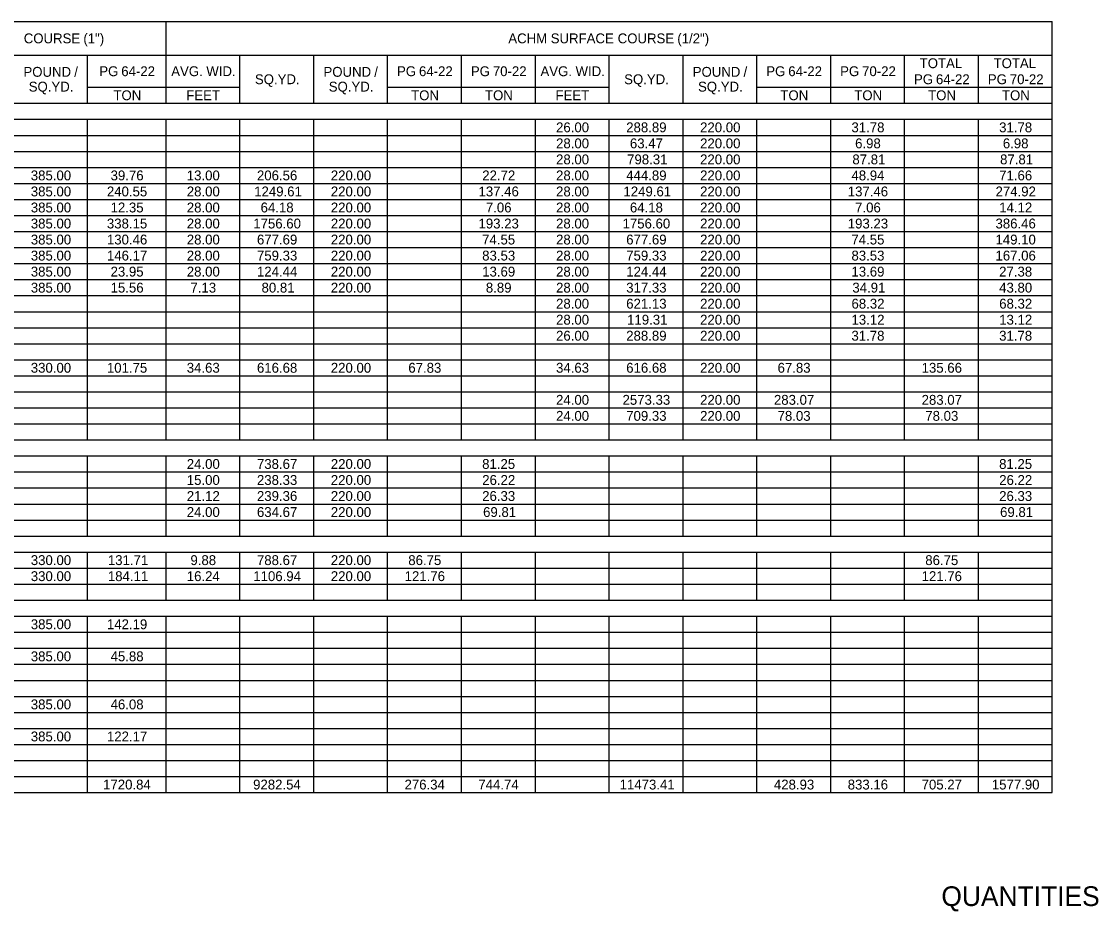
# Model space of a CAD drawing. Extents: x 1197542 to 1207068, y 230488 to 237324.
# Drawn here: x 1202635 to 1203290, y 231726 to 232267 of the extents above; entities that cross this region are included whole.
import ezdxf

# ---------------------------------------------------------------- set-up
doc = ezdxf.new("R2010")
doc.units = 0
doc.layers.add('Default', color=7, linetype='Continuous')
doc.layers.add('R_Annotation', color=7, linetype='Continuous')

msp = doc.modelspace()

# ---------------------------------------------------------------- linework, layer by layer
at = {"layer": 'Default'}
for p, q in [((1201719.44, 232267.45), (1203261.96, 232267.45)), ((1202722.83, 232246.98), (1202722.83, 232267.45)), ((1202722.83, 232217.73), (1202722.83, 232267.45)), ((1203261.96, 231808.23), (1203261.96, 232267.45)), ((1203261.96, 231798.48), (1203261.96, 232267.45)), ((1202088.22, 232246.98), (1203261.96, 232246.98)), ((1202675.09, 232217.73), (1202675.09, 232246.98)), ((1202767.76, 232246.98), (1202812.68, 232246.98)), ((1202767.76, 232217.73), (1202767.76, 232246.98)), ((1202812.68, 232217.73), (1202812.68, 232246.98)), ((1202857.61, 232217.73), (1202857.61, 232246.98)), ((1202902.54, 232217.73), (1202902.54, 232246.98)), ((1202947.47, 232217.73), (1202947.47, 232246.98)), ((1202992.4, 232246.98), (1203037.32, 232246.98)), ((1202992.4, 232217.73), (1202992.4, 232246.98)), ((1203037.32, 232217.73), (1203037.32, 232246.98)), ((1203082.25, 232217.73), (1203082.25, 232246.98)), ((1203127.18, 232217.73), (1203127.18, 232246.98)), ((1203172.11, 232217.73), (1203172.11, 232246.98)), ((1203217.04, 232217.73), (1203217.04, 232246.98)), ((1202675.09, 232227.48), (1202767.76, 232227.48)), ((1202722.83, 232217.73), (1202722.83, 232227.48)), ((1202767.76, 232217.73), (1202767.76, 232227.48)), ((1202857.61, 232227.48), (1202992.4, 232227.48)), ((1202947.47, 232217.73), (1202947.47, 232227.48)), ((1202992.4, 232217.73), (1202992.4, 232227.48)), ((1203082.25, 232227.48), (1203261.96, 232227.48)), ((1201719.44, 232217.73), (1203261.96, 232217.73)), ((1202585.24, 232217.73), (1202767.76, 232217.73)), ((1202767.76, 232217.73), (1202992.4, 232217.73)), ((1202992.4, 232217.73), (1203261.96, 232217.73)), ((1201719.44, 232207.98), (1203261.96, 232207.98)), ((1202675.09, 232012.98), (1202675.09, 232207.98)), ((1202675.09, 232012.98), (1202675.09, 232207.98)), ((1202722.83, 232012.98), (1202722.83, 232207.98)), ((1202722.83, 232012.98), (1202722.83, 232207.98)), ((1202767.76, 232012.98), (1202767.76, 232207.98)), ((1202767.76, 232012.98), (1202767.76, 232207.98)), ((1202812.68, 232012.98), (1202812.68, 232207.98)), ((1202812.68, 232012.98), (1202812.68, 232207.98)), ((1202857.61, 232012.98), (1202857.61, 232207.98)), ((1202857.61, 232012.98), (1202857.61, 232207.98)), ((1202902.54, 232012.98), (1202902.54, 232207.98)), ((1202902.54, 232012.98), (1202902.54, 232207.98)), ((1202947.47, 232012.98), (1202947.47, 232207.98)), ((1202947.47, 232012.98), (1202947.47, 232207.98)), ((1202992.4, 232012.98), (1202992.4, 232207.98)), ((1202992.4, 232012.98), (1202992.4, 232207.98)), ((1203037.32, 232012.98), (1203037.32, 232207.98)), ((1203037.32, 232012.98), (1203037.32, 232207.98)), ((1203082.25, 232012.98), (1203082.25, 232207.98)), ((1203082.25, 232012.98), (1203082.25, 232207.98)), ((1203127.18, 232012.98), (1203127.18, 232207.98)), ((1203127.18, 232012.98), (1203127.18, 232207.98)), ((1203172.11, 232012.98), (1203172.11, 232207.98)), ((1203172.11, 232012.98), (1203172.11, 232207.98)), ((1203217.04, 232012.98), (1203217.04, 232207.98)), ((1203217.04, 232012.98), (1203217.04, 232207.98)), ((1201719.44, 232198.23), (1203261.96, 232198.23)), ((1201719.44, 232188.48), (1203261.96, 232188.48)), ((1201719.44, 232178.73), (1203261.96, 232178.73)), ((1201719.44, 232168.98), (1203261.96, 232168.98)), ((1201719.44, 232159.23), (1203261.96, 232159.23)), ((1201719.44, 232149.48), (1203261.96, 232149.48)), ((1201719.44, 232139.73), (1203261.96, 232139.73)), ((1201719.44, 232129.98), (1203261.96, 232129.98)), ((1201719.44, 232120.23), (1203261.96, 232120.23)), ((1201719.44, 232110.48), (1203261.96, 232110.48)), ((1201719.44, 232100.73), (1203261.96, 232100.73)), ((1201719.44, 232090.98), (1203261.96, 232090.98)), ((1201719.44, 232081.23), (1203261.96, 232081.23)), ((1201719.44, 232071.48), (1203261.96, 232071.48)), ((1201719.44, 232061.73), (1203261.96, 232061.73)), ((1201719.44, 232051.98), (1203261.96, 232051.98)), ((1201719.44, 232042.23), (1203261.96, 232042.23)), ((1201719.44, 232032.48), (1203261.96, 232032.48)), ((1201719.44, 232022.73), (1203261.96, 232022.73)), ((1201719.44, 232012.98), (1202992.4, 232012.98)), ((1201719.44, 232012.98), (1203261.96, 232012.98)), ((1202992.4, 232012.98), (1203037.32, 232012.98)), ((1203037.32, 232012.98), (1203172.11, 232012.98)), ((1203172.11, 232012.98), (1203261.96, 232012.98)), ((1201719.44, 232003.23), (1203261.96, 232003.23)), ((1202675.09, 231954.48), (1202675.09, 232003.23)), ((1202675.09, 231954.48), (1202675.09, 232003.23)), ((1202722.83, 231954.48), (1202722.83, 232003.23)), ((1202722.83, 231954.48), (1202722.83, 232003.23)), ((1202767.76, 231954.48), (1202767.76, 232003.23)), ((1202767.76, 231954.48), (1202767.76, 232003.23)), ((1202812.68, 231954.48), (1202812.68, 232003.23)), ((1202812.68, 231954.48), (1202812.68, 232003.23)), ((1202857.61, 231954.48), (1202857.61, 232003.23)), ((1202857.61, 231954.48), (1202857.61, 232003.23)), ((1202902.54, 231954.48), (1202902.54, 232003.23)), ((1202902.54, 231954.48), (1202902.54, 232003.23)), ((1202947.47, 231954.48), (1202947.47, 232003.23)), ((1202947.47, 231954.48), (1202947.47, 232003.23)), ((1202992.4, 231954.48), (1202992.4, 232003.23)), ((1202992.4, 231954.48), (1202992.4, 232003.23)), ((1203037.32, 231954.48), (1203037.32, 232003.23)), ((1203037.32, 231954.48), (1203037.32, 232003.23)), ((1203082.25, 231954.48), (1203082.25, 232003.23)), ((1203082.25, 231954.48), (1203082.25, 232003.23)), ((1203127.18, 231954.48), (1203127.18, 232003.23)), ((1203127.18, 231954.48), (1203127.18, 232003.23)), ((1203172.11, 231954.48), (1203172.11, 232003.23)), ((1203172.11, 231954.48), (1203172.11, 232003.23)), ((1203217.04, 231954.48), (1203217.04, 232003.23)), ((1203217.04, 231954.48), (1203217.04, 232003.23)), ((1201719.44, 231993.48), (1203261.96, 231993.48)), ((1201719.44, 231983.73), (1203261.96, 231983.73)), ((1201719.44, 231973.98), (1203261.96, 231973.98)), ((1201719.44, 231964.23), (1203261.96, 231964.23)), ((1201719.44, 231954.48), (1203261.96, 231954.48)), ((1201719.44, 231954.48), (1203261.96, 231954.48)), ((1201719.44, 231944.73), (1203261.96, 231944.73)), ((1202675.09, 231915.48), (1202675.09, 231944.73)), ((1202675.09, 231915.48), (1202675.09, 231944.73)), ((1202722.83, 231915.48), (1202722.83, 231944.73)), ((1202722.83, 231915.48), (1202722.83, 231944.73)), ((1202767.76, 231915.48), (1202767.76, 231944.73)), ((1202767.76, 231915.48), (1202767.76, 231944.73)), ((1202812.68, 231915.48), (1202812.68, 231944.73)), ((1202812.68, 231915.48), (1202812.68, 231944.73)), ((1202857.61, 231915.48), (1202857.61, 231944.73)), ((1202857.61, 231915.48), (1202857.61, 231944.73)), ((1202902.54, 231915.48), (1202902.54, 231944.73)), ((1202902.54, 231915.48), (1202902.54, 231944.73)), ((1202947.47, 231915.48), (1202947.47, 231944.73)), ((1202947.47, 231915.48), (1202947.47, 231944.73)), ((1202992.4, 231915.48), (1202992.4, 231944.73)), ((1202992.4, 231915.48), (1202992.4, 231944.73)), ((1203037.32, 231915.48), (1203037.32, 231944.73)), ((1203037.32, 231915.48), (1203037.32, 231944.73)), ((1203082.25, 231915.48), (1203082.25, 231944.73)), ((1203082.25, 231915.48), (1203082.25, 231944.73)), ((1203127.18, 231915.48), (1203127.18, 231944.73)), ((1203127.18, 231915.48), (1203127.18, 231944.73)), ((1203172.11, 231915.48), (1203172.11, 231944.73)), ((1203172.11, 231915.48), (1203172.11, 231944.73)), ((1203217.04, 231915.48), (1203217.04, 231944.73)), ((1203217.04, 231915.48), (1203217.04, 231944.73)), ((1201719.44, 231934.98), (1203261.96, 231934.98)), ((1201719.44, 231925.23), (1203261.96, 231925.23)), ((1201719.44, 231915.48), (1202992.4, 231915.48)), ((1201719.44, 231915.48), (1203261.96, 231915.48)), ((1202992.4, 231915.48), (1203037.32, 231915.48)), ((1203037.32, 231915.48), (1203172.11, 231915.48)), ((1203172.11, 231915.48), (1203261.96, 231915.48)), ((1201719.44, 231905.73), (1203261.96, 231905.73)), ((1202675.09, 231798.48), (1202675.09, 231905.73)), ((1202675.09, 231798.48), (1202675.09, 231905.73)), ((1202722.83, 231798.48), (1202722.83, 231905.73)), ((1202722.83, 231798.48), (1202722.83, 231905.73)), ((1202767.76, 231798.48), (1202767.76, 231905.73)), ((1202767.76, 231798.48), (1202767.76, 231905.73)), ((1202812.68, 231798.48), (1202812.68, 231905.73)), ((1202812.68, 231798.48), (1202812.68, 231905.73)), ((1202857.61, 231798.48), (1202857.61, 231905.73)), ((1202857.61, 231798.48), (1202857.61, 231905.73)), ((1202902.54, 231798.48), (1202902.54, 231905.73)), ((1202902.54, 231798.48), (1202902.54, 231905.73)), ((1202947.47, 231798.48), (1202947.47, 231905.73)), ((1202947.47, 231798.48), (1202947.47, 231905.73)), ((1202992.4, 231798.48), (1202992.4, 231905.73)), ((1202992.4, 231798.48), (1202992.4, 231905.73)), ((1203037.32, 231798.48), (1203037.32, 231905.73)), ((1203037.32, 231798.48), (1203037.32, 231905.73)), ((1203082.25, 231798.48), (1203082.25, 231905.73)), ((1203082.25, 231798.48), (1203082.25, 231905.73)), ((1203127.18, 231798.48), (1203127.18, 231905.73)), ((1203127.18, 231798.48), (1203127.18, 231905.73)), ((1203172.11, 231798.48), (1203172.11, 231905.73)), ((1203172.11, 231798.48), (1203172.11, 231905.73)), ((1203217.04, 231798.48), (1203217.04, 231905.73)), ((1203217.04, 231798.48), (1203217.04, 231905.73)), ((1201719.44, 231895.98), (1203261.96, 231895.98)), ((1201719.44, 231886.23), (1203261.96, 231886.23)), ((1201719.44, 231876.48), (1203261.96, 231876.48)), ((1201719.44, 231866.73), (1203261.96, 231866.73)), ((1201719.44, 231856.98), (1203261.96, 231856.98)), ((1201719.44, 231847.23), (1203261.96, 231847.23)), ((1201719.44, 231837.48), (1203261.96, 231837.48)), ((1201719.44, 231827.73), (1203261.96, 231827.73)), ((1201719.44, 231817.98), (1203261.96, 231817.98)), ((1201719.44, 231808.23), (1203261.96, 231808.23)), ((1201719.44, 231808.23), (1203261.96, 231808.23)), ((1201719.44, 231798.48), (1203261.96, 231798.48))]:
    msp.add_line(p, q, dxfattribs=at)

# ---------------------------------------------------------------- texts
for s, p in [(' COURSE', (1202634.01, 232254.22)), (' (1")', (1202670.28, 232254.22)), ('ACHM', (1202931.02, 232254.22)), (' SURFACE', (1202954.59, 232254.22)), (' COURSE', (1202995.33, 232254.22)), (' (1/2")', (1203031.6, 232254.22)), ('POUND', (1202636.05, 232233.85)), (' /', (1202664.72, 232233.85)), ('PG', (1202682.19, 232234.23)), (' 64-22', (1202693.33, 232234.23)), ('AVG.', (1202725.95, 232234.23)), (' WID.', (1202745.07, 232234.23)), ('POUND', (1202818.57, 232233.85)), (' /', (1202847.24, 232233.85)), ('PG', (1202863.3, 232234.23)), (' 64-22', (1202874.45, 232234.23)), ('PG', (1202908.23, 232234.23)), (' 70-22', (1202919.37, 232234.23)), ('AVG.', (1202950.59, 232234.23)), (' WID.', (1202969.71, 232234.23)), ('POUND', (1203043.21, 232233.85)), (' /', (1203071.88, 232233.85)), ('PG', (1203087.94, 232234.23)), (' 64-22', (1203099.09, 232234.23)), ('PG', (1203132.87, 232234.23)), (' 70-22', (1203144.01, 232234.23)), ('TOTAL', (1203181.28, 232239.1)), ('TOTAL', (1203226.21, 232239.1)), ('SQ.YD.', (1202776.86, 232229.35)), ('SQ.YD.', (1203001.5, 232229.35)), ('PG', (1203177.8, 232229.35)), (' 64-22', (1203188.94, 232229.35)), ('PG', (1203222.73, 232229.35)), (' 70-22', (1203233.87, 232229.35)), ('SQ.YD.', (1202639.26, 232224.85)), ('SQ.YD.', (1202821.78, 232224.85)), ('SQ.YD.', (1203046.42, 232224.85)), ('TON', (1202690.79, 232219.6)), ('FEET', (1202735.09, 232219.6)), ('TON', (1202871.9, 232219.6)), ('TON', (1202916.83, 232219.6)), ('FEET', (1202959.73, 232219.6)), ('TON', (1203096.54, 232219.6)), ('TON', (1203141.47, 232219.6)), ('TON', (1203186.4, 232219.6)), ('TON', (1203231.33, 232219.6)), ('26.00', (1202960.06, 232200.1)), ('288.89', (1203002.74, 232200.1)), ('220.00', (1203047.68, 232200.1)), ('31.78', (1203139.76, 232200.1)), ('31.78', (1203229.61, 232200.1)), ('28.00', (1202960.06, 232190.35)), ('63.47', (1203004.98, 232190.35)), ('220.00', (1203047.68, 232190.35)), ('6.98', (1203141.99, 232190.35)), ('6.98', (1203231.85, 232190.35)), ('28.00', (1202960.06, 232180.6)), ('798.31', (1203003.3, 232180.6)), ('220.00', (1203047.68, 232180.6)), ('87.81', (1203140.32, 232180.6)), ('87.81', (1203230.18, 232180.6)), ('385.00', (1202640.52, 232170.85)), ('39.76', (1202689.08, 232170.85)), ('13.00', (1202735.42, 232170.85)), ('206.56', (1202778.1, 232170.85)), ('220.00', (1202823.04, 232170.85)), ('22.72', (1202915.15, 232170.85)), ('28.00', (1202960.06, 232170.85)), ('444.89', (1203002.74, 232170.85)), ('220.00', (1203047.68, 232170.85)), ('48.94', (1203139.77, 232170.85)), ('71.66', (1203229.62, 232170.85)), ('385.00', (1202640.52, 232161.1)), ('240.55', (1202686.82, 232161.1)), ('28.00', (1202735.42, 232161.1)), ('1249.61', (1202776.42, 232161.1)), ('220.00', (1202823.04, 232161.1)), ('137.46', (1202912.88, 232161.1)), ('28.00', (1202960.06, 232161.1)), ('1249.61', (1203001.06, 232161.1)), ('220.00', (1203047.68, 232161.1)), ('137.46', (1203137.52, 232161.1)), ('274.92', (1203227.41, 232161.1)), ('385.00', (1202640.52, 232151.35)), ('12.35', (1202689.06, 232151.35)), ('28.00', (1202735.42, 232151.35)), ('64.18', (1202780.33, 232151.35)), ('220.00', (1202823.04, 232151.35)), ('7.06', (1202917.36, 232151.35)), ('28.00', (1202960.06, 232151.35)), ('64.18', (1203004.97, 232151.35)), ('220.00', (1203047.68, 232151.35)), ('7.06', (1203142, 232151.35)), ('14.12', (1203229.65, 232151.35)), ('385.00', (1202640.52, 232141.6)), ('338.15', (1202686.82, 232141.6)), ('28.00', (1202735.42, 232141.6)), ('1756.60', (1202775.87, 232141.6)), ('220.00', (1202823.04, 232141.6)), ('193.23', (1202912.88, 232141.6)), ('28.00', (1202960.06, 232141.6)), ('1756.60', (1203000.51, 232141.6)), ('220.00', (1203047.68, 232141.6)), ('193.23', (1203137.52, 232141.6)), ('386.46', (1203227.38, 232141.6)), ('385.00', (1202640.52, 232131.85)), ('130.46', (1202686.84, 232131.85)), ('28.00', (1202735.42, 232131.85)), ('677.69', (1202778.1, 232131.85)), ('220.00', (1202823.04, 232131.85)), ('74.55', (1202915.1, 232131.85)), ('28.00', (1202960.06, 232131.85)), ('677.69', (1203002.74, 232131.85)), ('220.00', (1203047.68, 232131.85)), ('74.55', (1203139.74, 232131.85)), ('149.10', (1203227.39, 232131.85)), ('385.00', (1202640.52, 232122.1)), ('146.17', (1202686.84, 232122.1)), ('28.00', (1202735.42, 232122.1)), ('759.33', (1202778.1, 232122.1)), ('220.00', (1202823.04, 232122.1)), ('83.53', (1202915.12, 232122.1)), ('28.00', (1202960.06, 232122.1)), ('759.33', (1203002.74, 232122.1)), ('220.00', (1203047.68, 232122.1)), ('83.53', (1203139.76, 232122.1)), ('167.06', (1203227.38, 232122.1)), ('385.00', (1202640.52, 232112.35)), ('23.95', (1202689.06, 232112.35)), ('28.00', (1202735.42, 232112.35)), ('124.44', (1202778.11, 232112.35)), ('220.00', (1202823.04, 232112.35)), ('13.69', (1202915.12, 232112.35)), ('28.00', (1202960.06, 232112.35)), ('124.44', (1203002.75, 232112.35)), ('220.00', (1203047.68, 232112.35)), ('13.69', (1203139.76, 232112.35)), ('27.38', (1203229.61, 232112.35)), ('385.00', (1202640.52, 232102.6)), ('15.56', (1202689.08, 232102.6)), ('7.13', (1202737.65, 232102.6)), ('80.81', (1202780.9, 232102.6)), ('220.00', (1202823.04, 232102.6)), ('8.89', (1202917.35, 232102.6)), ('28.00', (1202960.06, 232102.6)), ('317.33', (1203002.74, 232102.6)), ('220.00', (1203047.68, 232102.6)), ('34.91', (1203140.32, 232102.6)), ('43.80', (1203229.63, 232102.6)), ('28.00', (1202960.06, 232092.85)), ('621.13', (1203002.74, 232092.85)), ('220.00', (1203047.68, 232092.85)), ('68.32', (1203139.79, 232092.85)), ('68.32', (1203229.65, 232092.85)), ('28.00', (1202960.06, 232083.1)), ('119.31', (1203003.3, 232083.1)), ('220.00', (1203047.68, 232083.1)), ('13.12', (1203139.79, 232083.1)), ('13.12', (1203229.65, 232083.1)), ('26.00', (1202960.06, 232073.35)), ('288.89', (1203002.74, 232073.35)), ('220.00', (1203047.68, 232073.35)), ('31.78', (1203139.76, 232073.35)), ('31.78', (1203229.61, 232073.35)), ('330.00', (1202640.52, 232053.85)), ('101.75', (1202686.82, 232053.85)), ('34.63', (1202735.41, 232053.85)), ('616.68', (1202778.1, 232053.85)), ('220.00', (1202823.04, 232053.85)), ('67.83', (1202870.19, 232053.85)), ('34.63', (1202960.05, 232053.85)), ('616.68', (1203002.74, 232053.85)), ('220.00', (1203047.68, 232053.85)), ('67.83', (1203094.83, 232053.85)), ('135.66', (1203182.45, 232053.85)), ('24.00', (1202960.06, 232034.35)), ('2573.33', (1203000.5, 232034.35)), ('220.00', (1203047.68, 232034.35)), ('283.07', (1203092.6, 232034.35)), ('283.07', (1203182.45, 232034.35)), ('24.00', (1202960.06, 232024.6)), ('709.33', (1203002.74, 232024.6)), ('220.00', (1203047.68, 232024.6)), ('78.03', (1203094.83, 232024.6)), ('78.03', (1203184.69, 232024.6)), ('24.00', (1202735.42, 231995.35)), ('738.67', (1202778.1, 231995.35)), ('220.00', (1202823.04, 231995.35)), ('81.25', (1202915.1, 231995.35)), ('81.25', (1203229.6, 231995.35)), ('15.00', (1202735.42, 231985.6)), ('238.33', (1202778.1, 231985.6)), ('220.00', (1202823.04, 231985.6)), ('26.22', (1202915.15, 231985.6)), ('26.22', (1203229.65, 231985.6)), ('21.12', (1202735.44, 231975.85)), ('239.36', (1202778.1, 231975.85)), ('220.00', (1202823.04, 231975.85)), ('26.33', (1202915.12, 231975.85)), ('26.33', (1203229.62, 231975.85)), ('24.00', (1202735.42, 231966.1)), ('634.67', (1202778.1, 231966.1)), ('220.00', (1202823.04, 231966.1)), ('69.81', (1202915.68, 231966.1)), ('69.81', (1203230.18, 231966.1)), ('330.00', (1202640.52, 231936.85)), ('131.71', (1202687.4, 231936.85)), ('9.88', (1202737.64, 231936.85)), ('788.67', (1202778.1, 231936.85)), ('220.00', (1202823.04, 231936.85)), ('86.75', (1202870.17, 231936.85)), ('86.75', (1203184.67, 231936.85)), ('330.00', (1202640.52, 231927.1)), ('184.11', (1202687.4, 231927.1)), ('16.24', (1202735.42, 231927.1)), ('1106.94', (1202775.88, 231927.1)), ('220.00', (1202823.04, 231927.1)), ('121.76', (1202867.96, 231927.1)), ('121.76', (1203182.45, 231927.1)), ('385.00', (1202640.52, 231897.85)), ('142.19', (1202686.84, 231897.85)), ('385.00', (1202640.52, 231878.35)), ('45.88', (1202689.07, 231878.35)), ('385.00', (1202640.52, 231849.1)), ('46.08', (1202689.07, 231849.1)), ('385.00', (1202640.52, 231829.6)), ('122.17', (1202686.84, 231829.6)), ('1720.84', (1202684.51, 231800.35)), ('9282.54', (1202775.77, 231800.35)), ('276.34', (1202867.87, 231800.35)), ('744.74', (1202912.79, 231800.35)), ('11473.41', (1202998.74, 231800.35)), ('428.93', (1203092.59, 231800.35)), ('833.16', (1203137.49, 231800.35)), ('705.27', (1203182.45, 231800.35)), ('1577.90', (1203225.16, 231800.35))]:
    msp.add_text(s, height=6, dxfattribs=at).set_placement(p)
at = {"layer": 'R_Annotation'}
msp.add_text('QUANTITIES', height=12, rotation=360, dxfattribs=at).set_placement((1203194.47, 231729.45))

doc.saveas('drawing.dxf')
